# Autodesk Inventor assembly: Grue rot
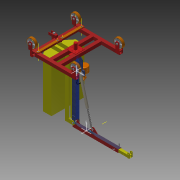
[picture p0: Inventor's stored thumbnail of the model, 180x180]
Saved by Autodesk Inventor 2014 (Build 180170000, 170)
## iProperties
Created: 2015-07
Part Number: Grue rot
Document SubType Name: Assembly
Designer: OL
Author: OL
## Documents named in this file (29)
- D:\Lycée Larmand\Profs\SUJET BAC EDPI ETC\ELABORATION SUJET EDPI\Bourgeois RT 510\Modele Grue rotative\Grue rot.iam
- D:\Lycée Larmand\Profs\SUJET BAC EDPI ETC\ELABORATION SUJET EDPI\Bourgeois RT 510\Modele Grue rotative\Cadre chariot.ipt
- D:\Lycée Larmand\Profs\SUJET BAC EDPI ETC\ELABORATION SUJET EDPI\Bourgeois RT 510\Modele Grue rotative\Axe.ipt
- D:\Lycée Larmand\Profs\SUJET BAC EDPI ETC\ELABORATION SUJET EDPI\Bourgeois RT 510\Modele Grue rotative\Poteau central.ipt
- D:\Lycée Larmand\Profs\SUJET BAC EDPI ETC\ELABORATION SUJET EDPI\Bourgeois RT 510\Modele Grue rotative\Potence pivot.ipt
- D:\Lycée Larmand\Profs\SUJET BAC EDPI ETC\ELABORATION SUJET EDPI\Bourgeois RT 510\Modele Grue rotative\Potence coulissante.ipt
- D:\Lycée Larmand\Profs\SUJET BAC EDPI ETC\ELABORATION SUJET EDPI\Bourgeois RT 510\Modele Grue rotative\Contrepoids.ipt
- D:\Lycée Larmand\Profs\SUJET BAC EDPI ETC\ELABORATION SUJET EDPI\Bourgeois RT 510\Modele Grue rotative\pompe\Pompe.ipt
- D:\Lycée Larmand\Profs\SUJET BAC EDPI ETC\ELABORATION SUJET EDPI\Bourgeois RT 510\Modele Grue rotative\Verin630-5-corps.ipt
- D:\Lycée Larmand\Profs\SUJET BAC EDPI ETC\ELABORATION SUJET EDPI\Bourgeois RT 510\Modele Grue rotative\Verin630-5-tige.ipt
- D:\Lycée Larmand\Profs\SUJET BAC EDPI ETC\ELABORATION SUJET EDPI\Bourgeois RT 510\Modele Grue rotative\Roue.ipt
- D:\Lycée Larmand\Profs\SUJET BAC EDPI ETC\ELABORATION SUJET EDPI\Bourgeois RT 510\Modele Grue rotative\Pivot de Direction.ipt
- D:\Lycée Larmand\Profs\SUJET BAC EDPI ETC\ELABORATION SUJET EDPI\Bourgeois RT 510\Modele Grue rotative\Palier de roue.ipt
- D:\Lycée Larmand\Profs\SUJET BAC EDPI ETC\ELABORATION SUJET EDPI\Bourgeois RT 510\Modele Grue rotative\Biellette.ipt
- D:\Lycée Larmand\Profs\SUJET BAC EDPI ETC\ELABORATION SUJET EDPI\Bourgeois RT 510\Modele Grue rotative\Vis H M10x20_02.ipt
- D:\Lycée Larmand\Profs\SUJET BAC EDPI ETC\ELABORATION SUJET EDPI\Bourgeois RT 510\Modele Grue rotative\Ecrou H M10x20_01.ipt
- D:\Lycée Larmand\Profs\SUJET BAC EDPI ETC\ELABORATION SUJET EDPI\Bourgeois RT 510\Modele Grue rotative\Axe D20.ipt
- D:\Lycée Larmand\Profs\SUJET BAC EDPI ETC\ELABORATION SUJET EDPI\Bourgeois RT 510\Modele Grue rotative\Goupille D20.ipt
- D:\Lycée Larmand\Profs\SUJET BAC EDPI ETC\ELABORATION SUJET EDPI\Bourgeois RT 510\Modele Grue rotative\Axe D20 L122.ipt
- D:\Lycée Larmand\Profs\SUJET BAC EDPI ETC\ELABORATION SUJET EDPI\Bourgeois RT 510\Modele Grue rotative\Rondelle d'appui D20.ipt
- D:\Lycée Larmand\Profs\SUJET BAC EDPI ETC\ELABORATION SUJET EDPI\Bourgeois RT 510\Modele Grue rotative\Axe D20 L96.ipt
- D:\Lycée Larmand\Profs\SUJET BAC EDPI ETC\ELABORATION SUJET EDPI\Bourgeois RT 510\Modele Grue rotative\Axe Roue D25 L116.ipt
- D:\Lycée Larmand\Profs\SUJET BAC EDPI ETC\ELABORATION SUJET EDPI\Bourgeois RT 510\Modele Grue rotative\Rondelle d'appui D25.ipt
- D:\Lycée Larmand\Profs\SUJET BAC EDPI ETC\ELABORATION SUJET EDPI\Bourgeois RT 510\Modele Grue rotative\Goupille D25.ipt
- D:\Lycée Larmand\Profs\SUJET BAC EDPI ETC\ELABORATION SUJET EDPI\Bourgeois RT 510\Modele Grue rotative\Butée manuelle.ipt
- D:\Lycée Larmand\Profs\SUJET BAC EDPI ETC\ELABORATION SUJET EDPI\Bourgeois RT 510\Modele Grue rotative\Goupille Cavalier.ipt
- D:\Lycée Larmand\Profs\SUJET BAC EDPI ETC\ELABORATION SUJET EDPI\Bourgeois RT 510\Modele Grue rotative\Bague d'arrêt D25.ipt
- D:\Lycée Larmand\Profs\SUJET BAC EDPI ETC\ELABORATION SUJET EDPI\Bourgeois RT 510\Modele Grue rotative\tuyau 1.ipt
- D:\Lycée Larmand\Profs\SUJET BAC EDPI ETC\ELABORATION SUJET EDPI\Bourgeois RT 510\Modele Grue rotative\tuyau 2.ipt
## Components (72 placed, 28 different names)
1. Cadre chariot:1 — Logement:1, Logement:9, Logement:10, Logement:12, Logement:13, Angle:1, Logement:37, Angle:12, Logement:38, Logement:39, Logement:42, Angle:15, Logement:43, Logement:44, Angle:16, Angle:17, Logement:54, Logement:74, Logement:75
2. Axe:1 — Logement:1, Logement:2
3. Poteau central:1 — Logement:2, Logement:3, Logement:4, Placage:3, Logement:5, Logement:6, Logement:7, Logement:21, Logement:22, Angle:3, Angle:6, Angle:7, Logement:27, Logement:28, Logement:57, Angle:20, Angle:22, Logement:58, Logement:60, Angle:24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
4. Potence pivot:1 — Logement:3, Placage:1, Placage:2, Tangente:1, Placage:11, Logement:32, Angle:9, Logement:33, Logement:34, Logement:62, Angle:28, Angle:34
5. Potence coulissante:1 — Placage:1, Placage:2, Tangente:1
6. Contrepoids:1 — Logement:4, Placage:3, Angle:1, Angle:2, Logement:25, Logement:30, Logement:31
7. Pompe:1 — Logement:5, Logement:6, Logement:20, Logement:56, Angle:21, Angle:23, Logement:59, Logement:61, Angle:26, Angle:27, Logement:72
8. Verin630-5-corps:1 — Logement:7, Placage:4, Logement:73
9. Verin630-5-tige:1 — Placage:4, Placage:10
10. Roue:1 — Logement:9
11. Roue:2 — Logement:10
12. Pivot de Direction:1 — Logement:54, Logement:63, Angle:30, Angle:31, Placage:19, Placage:20
13. Palier de roue:1 — Logement:12, Logement:17, Logement:18, Placage:6, Angle:19, Logement:49, Logement:50, Logement:53, Placage:17, Angle:33
14. Palier de roue:2 — Logement:13, Logement:19, Angle:2, Placage:5, Logement:47, Angle:18, Logement:51, Logement:52, Logement:55, Placage:18, Angle:32
15. Biellette:1 — Logement:17, Placage:14, Logement:64, Logement:70
16. Biellette:2 — Logement:55, Placage:13, Logement:65, Logement:68
17. Roue:3 — Logement:18
18. Roue:4 — Logement:19
19. Vis H M10x20_02:1 — Logement:20, Angle:23
20. Ecrou H M10x20_01:1 — Logement:21, Angle:22
21. Axe D20:1 — Logement:22, Angle:3, Logement:23, Angle:4, Logement:24, Angle:5, Placage:24
22. Goupille D20:1 — Logement:24, Angle:5
23. Goupille D20:2 — Logement:23, Angle:4
24. Goupille D20:3 — Logement:26, Angle:7
25. Goupille D20:4 — Logement:29, Angle:8
26. Axe D20 L122:1 — Logement:25, Logement:26, Angle:6, Logement:29, Angle:8
27. Rondelle d'appui D20:1 — Logement:27
28. Rondelle d'appui D20:2 — Logement:28
29. Rondelle d'appui D20:3 — Logement:30
30. Rondelle d'appui D20:4 — Logement:31
31. Axe D20 L96:1 — Logement:32, Angle:9, Logement:35, Angle:10, Logement:36, Angle:11, Placage:23
32. Rondelle d'appui D20:5 — Logement:34
33. Rondelle d'appui D20:6 — Logement:33
34. Goupille D20:5 — Logement:35, Angle:10
35. Goupille D20:6 — Logement:36, Angle:11
36. Axe Roue D25 L116:1 — Logement:37, Angle:12, Angle:13, Angle:14
37. Rondelle d'appui D25:1 — Logement:38, Logement:41
38. Rondelle d'appui D25:2 — Logement:39, Logement:40
39. Goupille D25:1 — Logement:41, Angle:14
40. Goupille D25:2 — Logement:40, Angle:13
41. Axe Roue D25 L116:2 — Logement:42, Angle:15
42. Rondelle d'appui D25:3 — Logement:44, Logement:45
43. Rondelle d'appui D25:4 — Logement:43, Logement:46
44. Goupille D25:3 — Logement:45, Angle:16
45. Goupille D25:4 — Logement:46, Angle:17
46. Axe Roue D25 L116:3 — Logement:47, Angle:18
47. Axe Roue D25 L116:4 — Angle:19, Logement:53
48. Rondelle d'appui D25:5 — Logement:49
49. Rondelle d'appui D25:6 — Logement:50
50. Rondelle d'appui D25:7 — Logement:52
51. Rondelle d'appui D25:8 — Logement:51
52. Vis H M10x20_02:2 — Logement:56, Angle:21
53. Ecrou H M10x20_01:2 — Logement:57, Angle:20
54. Vis H M10x20_02:3 — Logement:59, Angle:26
55. Ecrou H M10x20_01:3 — Logement:58, Angle:24
56. Vis H M10x20_02:4 — Logement:61, Angle:27
57. Ecrou H M10x20_01:4 — Logement:60, Angle:25
58. Butée manuelle:1 — Logement:62, Angle:28, Placage:15, Affleurement:1, Angle:29
59. Goupille Cavalier:1 — Placage:16, Affleurement:1, Angle:29
60. Bague d'arrêt D25:1 — Logement:63
61. Rondelle d'appui D20:7 — Logement:65, Logement:66, Placage:22
62. Rondelle d'appui D20:8 — Logement:64, Logement:67
63. Goupille D20:7 — Logement:66, Angle:30
64. Goupille D20:8 — Logement:67, Angle:31
65. Goupille D20:9 — Logement:69, Angle:32
66. Rondelle d'appui D20:9 — Logement:68, Logement:69
67. Rondelle d'appui D20:10 — Logement:70, Logement:71
68. Goupille D20:10 — Logement:71, Angle:33
69. tuyau 1:1 — Logement:72, Tangente:2
70. tuyau 2:1 — Logement:73, Tangente:2
71. Bague d'arrêt D25:2 — Logement:74
72. Bague d'arrêt D25:3 — Logement:75
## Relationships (125: Insert 69, Angle 34, Mate 19, Tangent 2, Flush 1)
- Logement:1 [Insert]: Cadre chariot:1 ↔ Axe:1
- Logement:2 [Insert]: Axe:1 ↔ Poteau central:1
- Logement:3 [Insert]: Poteau central:1 ↔ Potence pivot:1
- Placage:1 [Mate]: Potence pivot:1 ↔ Potence coulissante:1
- Placage:2 [Mate]: Potence pivot:1 ↔ Potence coulissante:1
- Logement:4 [Insert]: Poteau central:1 ↔ Contrepoids:1
- Placage:3 [Mate]: Poteau central:1 ↔ Contrepoids:1
- Logement:5 [Insert]: Poteau central:1 ↔ Pompe:1
- Logement:6 [Insert]: Poteau central:1 ↔ Pompe:1
- Logement:7 [Insert]: Poteau central:1 ↔ Verin630-5-corps:1
- Placage:4 [Mate]: Verin630-5-corps:1 ↔ Verin630-5-tige:1
- Tangente:1: Potence pivot:1 ↔ Potence coulissante:1
- Logement:9 [Insert]: Cadre chariot:1 ↔ Roue:1
- Logement:10 [Insert]: Cadre chariot:1 ↔ Roue:2
- Logement:12 [Insert]: Cadre chariot:1 ↔ Palier de roue:1
- Logement:13 [Insert]: Cadre chariot:1 ↔ Palier de roue:2
- Logement:17 [Insert]: Palier de roue:1 ↔ Biellette:1
- Logement:18 [Insert]: Palier de roue:1 ↔ Roue:3
- Logement:19 [Insert]: Palier de roue:2 ↔ Roue:4
- Angle:1: Cadre chariot:1 ↔ Contrepoids:1
- Angle:2: Contrepoids:1 ↔ Palier de roue:2
- Placage:5 [Mate]: Palier de roue:2
- Placage:6 [Mate]: Palier de roue:1
- Logement:20 [Insert]: Pompe:1 ↔ Vis H M10x20_02:1
- Logement:21 [Insert]: Poteau central:1 ↔ Ecrou H M10x20_01:1
- Logement:22 [Insert]: Poteau central:1 ↔ Axe D20:1
- Angle:3: Poteau central:1 ↔ Axe D20:1
- Logement:23 [Insert]: Axe D20:1 ↔ Goupille D20:2
- Angle:4: Axe D20:1 ↔ Goupille D20:2
- Logement:24 [Insert]: Axe D20:1 ↔ Goupille D20:1
- Angle:5: Axe D20:1 ↔ Goupille D20:1
- Placage:10 [Mate]: Verin630-5-tige:1
- Placage:11 [Mate]: Potence pivot:1
- Logement:25 [Insert]: Contrepoids:1 ↔ Axe D20 L122:1
- Logement:26 [Insert]: Goupille D20:3 ↔ Axe D20 L122:1
- Angle:6: Poteau central:1 ↔ Axe D20 L122:1
- Angle:7: Poteau central:1 ↔ Goupille D20:3
- Logement:27 [Insert]: Poteau central:1 ↔ Rondelle d'appui D20:1
- Logement:28 [Insert]: Poteau central:1 ↔ Rondelle d'appui D20:2
- Logement:29 [Insert]: Goupille D20:4 ↔ Axe D20 L122:1
- Angle:8: Goupille D20:4 ↔ Axe D20 L122:1
- Logement:30 [Insert]: Contrepoids:1 ↔ Rondelle d'appui D20:3
- Logement:31 [Insert]: Contrepoids:1 ↔ Rondelle d'appui D20:4
- Logement:32 [Insert]: Potence pivot:1 ↔ Axe D20 L96:1
- Angle:9: Potence pivot:1 ↔ Axe D20 L96:1
- Logement:33 [Insert]: Potence pivot:1 ↔ Rondelle d'appui D20:6
- Logement:34 [Insert]: Potence pivot:1 ↔ Rondelle d'appui D20:5
- Logement:35 [Insert]: Axe D20 L96:1 ↔ Goupille D20:5
- Angle:10: Axe D20 L96:1 ↔ Goupille D20:5
- Logement:36 [Insert]: Axe D20 L96:1 ↔ Goupille D20:6
- Angle:11: Axe D20 L96:1 ↔ Goupille D20:6
- Logement:37 [Insert]: Cadre chariot:1 ↔ Axe Roue D25 L116:1
- Angle:12: Cadre chariot:1 ↔ Axe Roue D25 L116:1
- Logement:38 [Insert]: Cadre chariot:1 ↔ Rondelle d'appui D25:1
- Logement:39 [Insert]: Cadre chariot:1 ↔ Rondelle d'appui D25:2
- Logement:40 [Insert]: Rondelle d'appui D25:2 ↔ Goupille D25:2
- Angle:13: Axe Roue D25 L116:1 ↔ Goupille D25:2
- Logement:41 [Insert]: Rondelle d'appui D25:1 ↔ Goupille D25:1
- Angle:14: Axe Roue D25 L116:1 ↔ Goupille D25:1
- Logement:42 [Insert]: Cadre chariot:1 ↔ Axe Roue D25 L116:2
- Angle:15: Cadre chariot:1 ↔ Axe Roue D25 L116:2
- Logement:43 [Insert]: Cadre chariot:1 ↔ Rondelle d'appui D25:4
- Logement:44 [Insert]: Cadre chariot:1 ↔ Rondelle d'appui D25:3
- Logement:45 [Insert]: Rondelle d'appui D25:3 ↔ Goupille D25:3
- Angle:16: Cadre chariot:1 ↔ Goupille D25:3
- Logement:46 [Insert]: Rondelle d'appui D25:4 ↔ Goupille D25:4
- Angle:17: Cadre chariot:1 ↔ Goupille D25:4
- Logement:47 [Insert]: Palier de roue:2 ↔ Axe Roue D25 L116:3
- Angle:18: Palier de roue:2 ↔ Axe Roue D25 L116:3
- Angle:19: Palier de roue:1 ↔ Axe Roue D25 L116:4
- Logement:49 [Insert]: Palier de roue:1 ↔ Rondelle d'appui D25:5
- Logement:50 [Insert]: Palier de roue:1 ↔ Rondelle d'appui D25:6
- Logement:51 [Insert]: Palier de roue:2 ↔ Rondelle d'appui D25:8
- Logement:52 [Insert]: Palier de roue:2 ↔ Rondelle d'appui D25:7
- Logement:53 [Insert]: Palier de roue:1 ↔ Axe Roue D25 L116:4
- Logement:54 [Insert]: Cadre chariot:1 ↔ Pivot de Direction:1
- Logement:55 [Insert]: Palier de roue:2 ↔ Biellette:2
- Placage:13 [Mate]: Biellette:2
- Placage:14 [Mate]: Biellette:1
- Logement:56 [Insert]: Pompe:1 ↔ Vis H M10x20_02:2
- Logement:57 [Insert]: Poteau central:1 ↔ Ecrou H M10x20_01:2
- Angle:20: Poteau central:1 ↔ Ecrou H M10x20_01:2
- Angle:21: Pompe:1 ↔ Vis H M10x20_02:2
- Angle:22: Poteau central:1 ↔ Ecrou H M10x20_01:1
- Angle:23: Pompe:1 ↔ Vis H M10x20_02:1
- Logement:58 [Insert]: Poteau central:1 ↔ Ecrou H M10x20_01:3
- Logement:59 [Insert]: Pompe:1 ↔ Vis H M10x20_02:3
- Logement:60 [Insert]: Poteau central:1 ↔ Ecrou H M10x20_01:4
- Logement:61 [Insert]: Pompe:1 ↔ Vis H M10x20_02:4
- Angle:24: Poteau central:1 ↔ Ecrou H M10x20_01:3
- Angle:25: Poteau central:1 ↔ Ecrou H M10x20_01:4
- Angle:26: Pompe:1 ↔ Vis H M10x20_02:3
- Angle:27: Pompe:1 ↔ Vis H M10x20_02:4
- Logement:62 [Insert]: Potence pivot:1 ↔ Butée manuelle:1
- Angle:28: Potence pivot:1 ↔ Butée manuelle:1
- Placage:15 [Mate]: Butée manuelle:1
- Placage:16 [Mate]: Goupille Cavalier:1
- Affleurement:1 [Flush]: Butée manuelle:1 ↔ Goupille Cavalier:1
- Angle:29: Butée manuelle:1 ↔ Goupille Cavalier:1
- Logement:63 [Insert]: Pivot de Direction:1 ↔ Bague d'arrêt D25:1
- Logement:64 [Insert]: Biellette:1 ↔ Rondelle d'appui D20:8
- Logement:65 [Insert]: Biellette:2 ↔ Rondelle d'appui D20:7
- Logement:66 [Insert]: Rondelle d'appui D20:7 ↔ Goupille D20:7
- Angle:30: Pivot de Direction:1 ↔ Goupille D20:7
- Logement:67 [Insert]: Rondelle d'appui D20:8 ↔ Goupille D20:8
- Angle:31: Pivot de Direction:1 ↔ Goupille D20:8
- Placage:17 [Mate]: Palier de roue:1
- Placage:18 [Mate]: Palier de roue:2
- Placage:19 [Mate]: Pivot de Direction:1
- Placage:20 [Mate]: Pivot de Direction:1
- Placage:22 [Mate]: Rondelle d'appui D20:7
- Logement:68 [Insert]: Biellette:2 ↔ Rondelle d'appui D20:9
- Logement:69 [Insert]: Goupille D20:9 ↔ Rondelle d'appui D20:9
- Angle:32: Palier de roue:2 ↔ Goupille D20:9
- Logement:70 [Insert]: Biellette:1 ↔ Rondelle d'appui D20:10
- Logement:71 [Insert]: Rondelle d'appui D20:10 ↔ Goupille D20:10
- Angle:33: Palier de roue:1 ↔ Goupille D20:10
- Logement:72 [Insert]: Pompe:1 ↔ tuyau 1:1
- Logement:73 [Insert]: Verin630-5-corps:1 ↔ tuyau 2:1
- Tangente:2: tuyau 1:1 ↔ tuyau 2:1
- Logement:74 [Insert]: Cadre chariot:1 ↔ Bague d'arrêt D25:2
- Logement:75 [Insert]: Cadre chariot:1 ↔ Bague d'arrêt D25:3
- Placage:23 [Mate]: Axe D20 L96:1
- Placage:24 [Mate]: Axe D20:1
- Angle:34: Poteau central:1 ↔ Potence pivot:1
